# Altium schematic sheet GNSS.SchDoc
size A3; CompanyName: Icoteq Ltd; Address1: Cambridge House; Address2: 1 Henry Street; Address3: Bath; Address4: BA1 1BT; DocumentNumber: GNSS Module; SheetNumber: 3
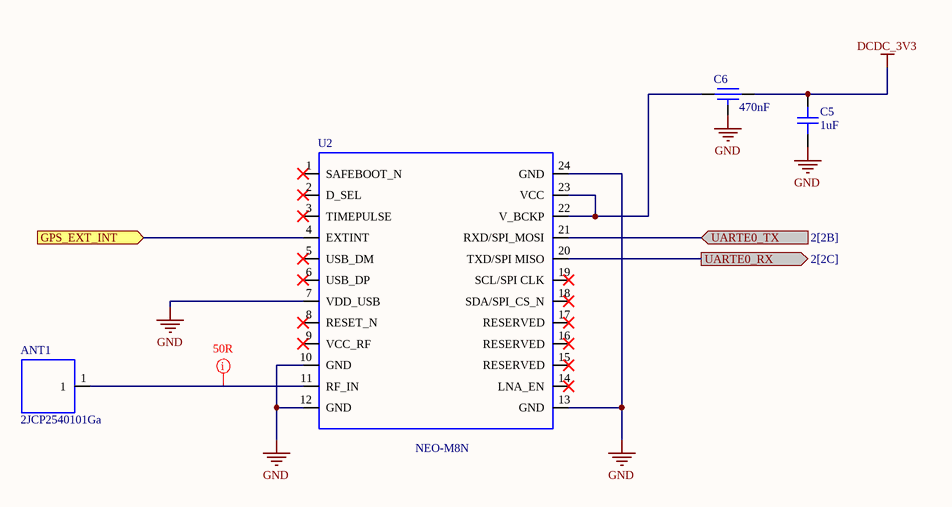
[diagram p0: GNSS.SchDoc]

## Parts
ANT1  2JCP2540101Ga  [2JCP2540101Ga]
C5  value 1uF  [CAP0201L]  (hidden comment: 1UF 0201 10V 20% X5R)
C6  value 470nF  [YFF15PC]  (hidden comment: 470NF 0402 6.3V +50%/-20%)
U2  NEO-M8N  [NEO]

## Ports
GPS_EXT_INT (in), UARTE0_RX (out, see 2[2C]), UARTE0_TX (in, see 2[2B])

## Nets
DCDC_3V3: C5.2 C6.2
GND: C5.1 C6.3 U2.7(VDD_USB) U2.10(GND) U2.12(GND) U2.13(GND) U2.24(GND)
GPS_EXT_INT: U2.4(EXTINT) ; port GPS_EXT_INT
UARTE0_RX: U2.20(TXD/SPI_MISO) ; port UARTE0_RX
UARTE0_TX: U2.21(RXD/SPI_MOSI) ; port UARTE0_TX
NetANT1_1: ANT1.1 U2.11(RF_IN)
NetC6_1: C6.1 U2.22(V_BCKP) U2.23(VCC)

Not connected (* = marked no-connect by the designer): U2 1(SAFEBOOT_N)* 2(D_SEL)* 3(TIMEPULSE)* 5(USB_DM)* 6(USB_DP)* 8(RESET_N)* 9(VCC_RF)* 14(LNA_EN)* 15(RESERVED)* 16(RESERVED)* 17(RESERVED)* 18(SDA/SPI_CS_N)* 19(SCL/SPI_CLK)*

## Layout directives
net class 50R_track: NetANT1_1

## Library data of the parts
ANT1 = 2JCP2540101Ga: GNSS ANTENNA CERAMIC PATCH GPS/GALILEO/GLONASS/BEIDOU; Manufacturer: 2J ANTENNAS; Manufacturers Part Number: 2JCP2540106Ca (2J66)
C5 = CAP CER 1UF 0201 10V 20% X5R: Manufacturer: Murata; Manufacturers Part Number: GRM033R61A105ME15D
C6 = CAP FEEDTHRU 470NF 0402 6.3V +50%/-20%: Manufacturer: TDK; Manufacturers Part Number: YFF15PC0J474M
U2 = NEO-M8N: IC GNSS NEO-M8N; Manufacturer: ublox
